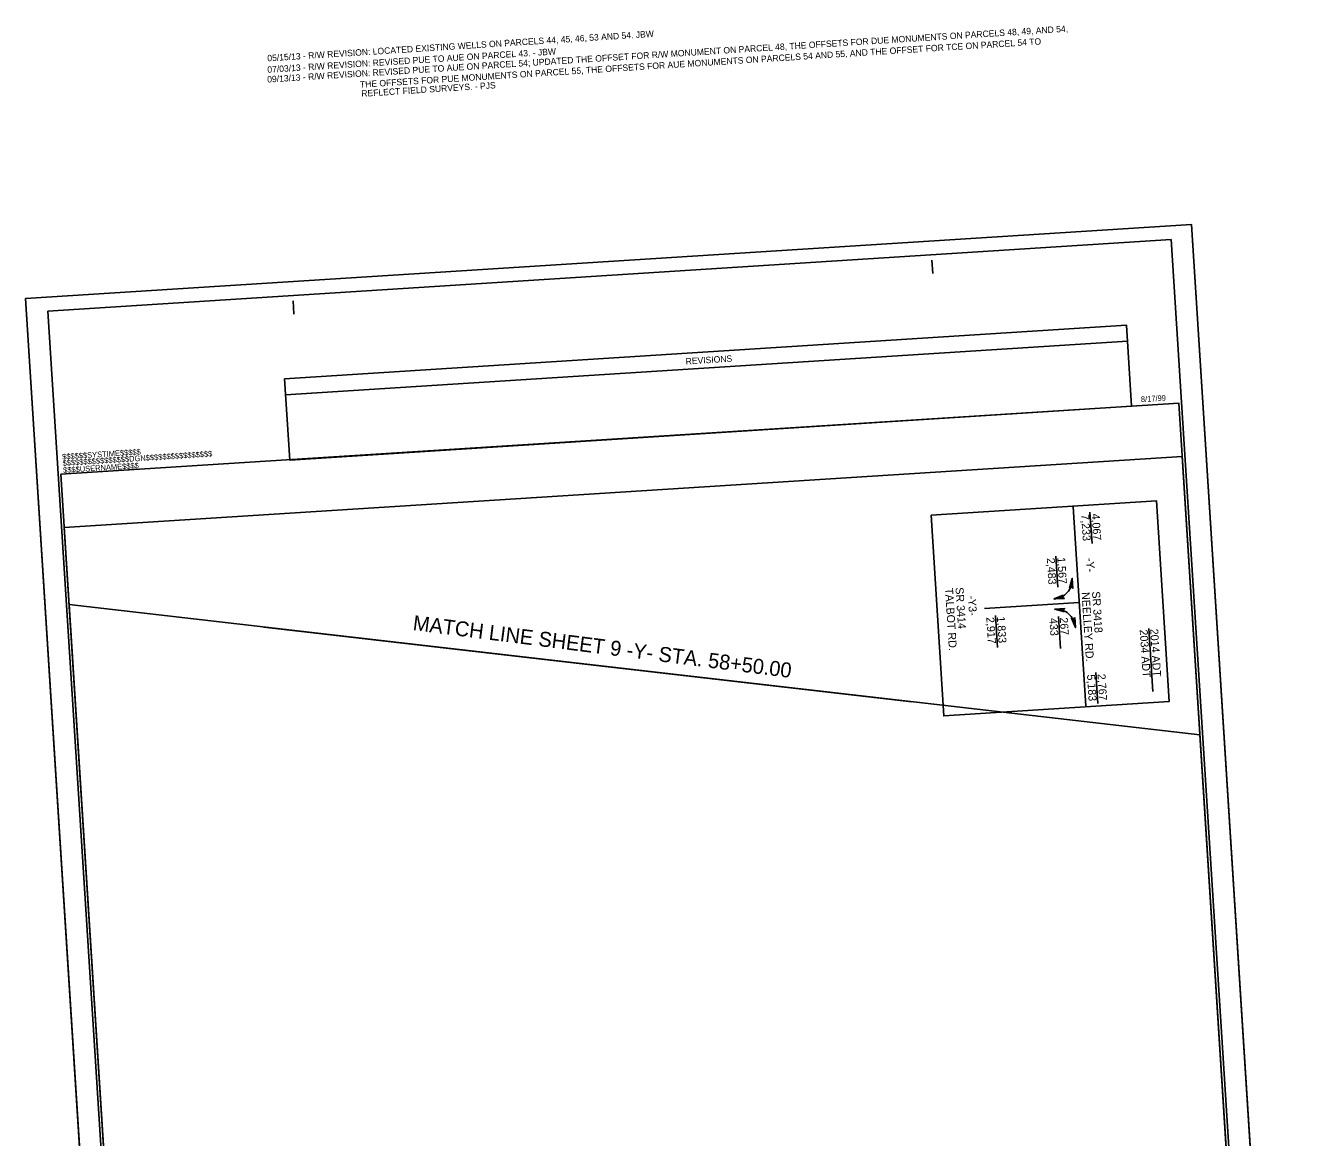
# Model space of a CAD drawing. Extents: x 1780418 to 1781618, y 810313 to 812397.
# Drawn here: x 1780418 to 1781618, y 811355 to 812397 of the extents above; entities that cross this region are included whole.
import ezdxf

# ---------------------------------------------------------------- set-up
doc = ezdxf.new("R2010")
doc.units = 0
for name, color, linetype in [('Prop Easement Aerial Utility', 7, 'Continuous'), ('Prop Easement Construction', 7, 'Continuous'), ('Prop Easement Construction Station Offsets', 7, 'Continuous'), ('Prop Easement Permanent Utility', 7, 'Continuous'), ('Prop Easement Permanent Utility Station Offsets', 7, 'Continuous'), ('Prop Easement Temporary Drainage', 7, 'Continuous'), ('Prop Easement Temporary Utility', 7, 'Continuous'), ('Prop Easement Temporary Utility Station Offsets', 7, 'Continuous'), ('Prop ROW CA Lines', 7, 'Continuous'), ('Prop ROW Marker CELL', 7, 'Continuous'), ('Prop ROW Station Offsets', 7, 'Continuous')]:
    doc.layers.add(name, color=color, linetype=linetype)

msp = doc.modelspace()

# ---------------------------------------------------------------- linework, layer by layer
at = {"layer": 'Prop Easement Aerial Utility'}
for p, q in [((1781511, 812211), (1780418.2, 812141.5)), ((1781617.8, 810530.9), (1781511, 812211)), ((1780418.2, 812141.5), (1780525, 810461.4))]:
    msp.add_line(p, q, dxfattribs=at)
at = {"layer": 'Prop Easement Construction'}
msp.add_line((1780662, 812051.2), (1781451, 812101.4), dxfattribs=at)
msp.add_lwpolyline([(1780661, 812066.1), (1781450, 812116.6), (1781454.9, 812040.6), (1780665.9, 811990.1)], close=True, dxfattribs=at)
at = {"layer": 'Prop Easement Permanent Utility'}
msp.add_lwpolyline([(1780454.4, 811926.9), (1780543.2, 810529.7), (1781380.1, 810582.9), (1781368.1, 810771.8), (1781579.1, 810785.2), (1781502.3, 811993.5)], close=True, dxfattribs=at)
at = {"layer": 'Prop Easement Permanent Utility Station Offsets'}
for p, q in [((1781412, 811759.6), (1781400, 811946.3)), ((1781415.9, 811941.1), (1781417.8, 811912)), ((1781383.9, 811900), (1781385.8, 811871)), ((1781317, 811850.8), (1781405.8, 811856.5)), ((1781327.2, 811844.5), (1781329.2, 811814.4)), ((1781386.3, 811843.6), (1781388.3, 811813.4)), ((1781471, 811832.1), (1781474.8, 811773)), ((1781421.4, 811790.9), (1781423.3, 811761.8))]:
    msp.add_line(p, q, dxfattribs=at)
for points in [[(1781266.9, 811938.5), (1781478.2, 811951.9), (1781490.1, 811763.7), (1781278.9, 811750.3)], [(1781399.9, 811869.8), (1781399.2, 811879.2), (1781396.7, 811870.1), (1781398.5, 811871.1)], [(1781390.9, 811863.4), (1781382.2, 811859.9), (1781391.7, 811860.2), (1781390.1, 811861.6)], [(1781391.9, 811847.9), (1781382.8, 811850.3), (1781392.2, 811851.1), (1781390.9, 811849.5)], [(1781401.7, 811842.5), (1781402.2, 811833.1), (1781398.5, 811841.8), (1781400.4, 811841)]]:
    msp.add_lwpolyline(points, close=True, dxfattribs=at)
for centre, start, end in [((1781381.1, 811878), 318.0413, 2.3931), ((1781381.1, 811878), 273.6894, 318.0413), ((1781384, 811832.2), 49.3353, 93.6872), ((1781384, 811832.2), 4.9834, 49.3353)]:
    msp.add_arc(centre, 18.2, start, end, dxfattribs=at)
at = {"layer": 'Prop Easement Temporary Drainage'}
for p, q in [((1781267.7, 812177.5), (1781268.5, 812165)), ((1780668.9, 812139.4), (1780669.7, 812126.9)), ((1781499.2, 812043.4), (1781499.2, 812043.4)), ((1780451.3, 811976.8), (1780451.3, 811976.8))]:
    msp.add_line(p, q, dxfattribs=at)
for points in [[(1781594.3, 810546.4), (1781499.2, 812043.4), (1780451.3, 811976.8), (1780546.4, 810479.8)], [(1780451.3, 811976.8), (1781499.1, 812043.4), (1781581.6, 810746.1), (1781431.9, 810736.5), (1781444.5, 810536.9), (1780546.4, 810479.8)]]:
    msp.add_lwpolyline(points, close=True, dxfattribs=at)
at = {"layer": 'Prop Easement Temporary Utility'}
msp.add_lwpolyline([(1781499.1, 812043.4), (1780451.3, 811976.8), (1780546.4, 810479.8), (1781383.2, 810533), (1781368.1, 810771.8), (1781579.1, 810785.2)], close=True, dxfattribs=at)
at = {"layer": 'Prop Easement Temporary Utility Station Offsets'}
msp.add_line((1780641.6, 811833.6), (1781248.8, 811763.6), dxfattribs=at)
at = {"layer": 'Prop ROW CA Lines'}
msp.add_lwpolyline([(1780418.2, 812141.5), (1780525, 810461.4), (1781617.8, 810530.9), (1781511, 812211)], close=True, dxfattribs=at)
at = {"layer": 'Prop ROW Marker CELL'}
msp.add_lwpolyline([(1781518.9, 811732.4), (1780459, 811854.7), (1780543.2, 810529.7), (1781420.7, 810585.5), (1781408.7, 810774.4), (1781579.1, 810785.2)], close=True, dxfattribs=at)
at = {"layer": 'Prop ROW Station Offsets'}
msp.add_lwpolyline([(1780439, 812129.8), (1780544.7, 810467.2), (1781597.6, 810534.1), (1781491.9, 812196.7)], close=True, dxfattribs=at)

# ---------------------------------------------------------------- texts
at = {"layer": 'Prop Easement Construction'}
for s, rotation, p in [('09/13/13 - R/W REVISION: REVISED PUE TO AUE ON PARCEL 54; UPDATED THE OFFSET FOR R/W MONUMENT ON PARCEL 48, THE OFFSETS FOR DUE MONUMENTS ON PARCELS 48, 49, AND 54,', 3.6364, (1780644.9, 812343.9)), ('05/15/13 - R/W REVISION: LOCATED EXISTING WELLS ON PARCELS 44, 45, 46, 53 AND 54. JBW ', 3.6364, (1780645, 812363.8)), ('THE OFFSETS FOR PUE MONUMENTS ON PARCEL 55, THE OFFSETS FOR AUE MONUMENTS ON PARCELS 54 AND 55, AND THE OFFSET FOR TCE ON PARCEL 54 TO', 3.6364, (1780731.8, 812339.1)), ('07/03/13 - R/W REVISION: REVISED PUE TO AUE ON PARCEL 43. - JBW', 3.6364, (1780645, 812353.1)), ('REFLECT FIELD SURVEYS. - PJS', 3.6364, (1780733.1, 812330.6)), ('REVISIONS', 3.6363, (1781037.1, 812079.6))]:
    msp.add_text(s, height=6, rotation=rotation, dxfattribs=at).set_placement(p)
at = {"layer": 'Prop Easement Construction Station Offsets'}
msp.add_text('MATCH LINE SHEET 9 -Y- STA. 58+50.00', height=14, rotation=352.7698, dxfattribs=at).set_placement((1780780.7, 811830.8))
at = {"layer": 'Prop Easement Permanent Utility Station Offsets'}
for s, rotation, p in [('4,067', 273.6365, (1781417.4, 811939.7)), ('7,233', 273.6365, (1781407.6, 811939.1)), ('2,483', 273.6365, (1781375.4, 811898.2)), ('1,567', 273.6365, (1781385.2, 811898.8)), ('-Y-', 274.1622, (1781412, 811898.1)), ('TALBOT RD.', 273.6365, (1781280, 811870)), ('SR 3414', 273.6365, (1781289.8, 811870.6)), ('-Y3-', 273.468, (1781301.4, 811863)), ('NEELLEY RD.', 273.6884, (1781408, 811866.1)), ('SR 3418', 273.6884, (1781417.8, 811866.8)), ('2,917', 273.6365, (1781318.7, 811842.7)), ('1,833', 273.6365, (1781328.6, 811843.3)), ('433', 273.6365, (1781377.8, 811841.8)), ('267', 273.6365, (1781387.6, 811842.4)), (' 2034 ADT', 273.6365, (1781462.3, 811833.8)), (' 2014 ADT', 273.6365, (1781472.1, 811834.5)), ('5,183', 273.6365, (1781413.1, 811788.9)), ('2,767', 273.6365, (1781422.9, 811789.5))]:
    msp.add_text(s, height=7.5, rotation=rotation, dxfattribs=at).set_placement(p)
at = {"layer": 'Prop Easement Temporary Drainage'}
for s, p in [('8/17/99', (1781463.8, 812044.4)), ('$$$$$$SYSTIME$$$$$', (1780452.7, 811990.6)), ('$$$$$$$$$$$$$$$$DGN$$$$$$$$$$$$$$$$', (1780453.1, 811984.6)), ('$$$$USERNAME$$$$', (1780453.6, 811978))]:
    msp.add_text(s, height=5.25, rotation=3.6363, dxfattribs=at).set_placement(p)

doc.saveas('drawing.dxf')
